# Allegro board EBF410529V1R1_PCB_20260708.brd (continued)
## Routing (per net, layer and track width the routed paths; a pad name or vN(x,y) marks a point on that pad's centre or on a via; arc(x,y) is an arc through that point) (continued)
HDMI_TX_D3P_PORT: length 18.5
  BOTTOM w0.107: C222.2 105.76,63.27 arc(105.56,63.57) 105.49,63.92 105.49,64.5 arc(105.56,64.85) 105.76,65.15 R228.1 105.9,65.58 arc(105.8,65.73) 105.77,65.9 D51.2 105.57,66.5 arc(105.51,66.58) 105.49,66.69 105.49,69.63 arc(105.43,69.9) 105.28,70.13 104.68,70.73 102.92,72.49 102.52,72.9 arc(102.42,73.04) 102.38,73.22 102.38,74.83 arc(102.31,75.21) 102.09,75.53 101.96,75.67 arc(101.77,75.79) 101.55,75.84 99.05,75.84 arc(98.78,75.89) 98.54,76.05 J33.10
HDMI_TX_EARC+: length 14.4
  BOTTOM w0.107: J33.14 98.51,73.77 arc(98.82,73.3) 98.93,72.74 98.93,71.56 arc(98.92,71.41) 98.87,71.27 arc(98.81,71.16) 98.73,71.07 arc(98.5,70.73) 98.42,70.34 98.42,69.31 arc(98.6,68.89) 99.03,68.71 101.05,68.71 arc(101.17,68.74) 101.28,68.81 101.3,68.83 arc(101.37,68.94) 101.4,69.06 arc(101.53,69.39) 101.86,69.52 102.24,69.52 arc(102.74,69.32) 102.95,68.82 102.95,66.68 arc(102.97,66.58) 103.02,66.5 D44.2 103.12,66.18 arc(103.07,66.1) 103.05,66.01 103.05,65.99 arc(103.07,65.9) 103.12,65.83 C224.2
HDMI_TX_EARC-: length 16.6
  BOTTOM w0.107: R149.2 101.6,63.49 101.6,64.9 102.11,65.41 C225.2 102.62,65.44 arc(102.72,65.48) 102.76,65.58 102.76,65.76 arc(102.73,65.9) 102.65,66.03 D31.2 102.55,66.46 arc(102.63,66.59) 102.66,66.74 102.66,66.81 arc(102.63,66.89) 102.55,66.92 arc(102.47,66.95) 102.44,67.03 102.44,67.24 arc(102.47,67.32) 102.55,67.35 arc(102.63,67.38) 102.66,67.46 102.66,67.73 arc(102.63,67.81) 102.55,67.84 arc(102.47,67.88) 102.44,67.96 102.44,68.16 arc(102.47,68.24) 102.55,68.27 arc(102.63,68.3) 102.66,68.38 102.66,68.82 arc(102.54,69.12) 102.24,69.24 101.86,69.24 arc(101.73,69.19) 101.68,69.06 arc(101.63,68.83) 101.5,68.63 101.48,68.61 arc(101.28,68.47) 101.05,68.43 100.81,68.43 arc(100.74,68.4) 100.71,68.33 arc(100.68,68.25) 100.61,68.22 100.28,68.22 arc(100.21,68.25) 100.18,68.33 arc(100.15,68.4) 100.08,68.43 99.03,68.43 arc(98.4,68.69) 98.14,69.31 98.14,69.77 arc(98.1,69.87) 98,69.91 arc(97.91,69.95) 97.87,70.04 97.87,70.19 arc(97.91,70.29) 98,70.33 arc(98.1,70.37) 98.14,70.47 98.14,70.65 arc(98.09,70.92) 97.93,71.16 97.82,71.27 arc(97.67,71.33) 97.52,71.27 J33.19
HDMI_TX_HPDIN_M0: length 182.3
  TOP w0.107: v1(44.5,59.05) 45.44,58.1 J3.125 ; Q8.3 v1(109.02,53.84) R141.2
  ART03 w0.107: v1(108.91,8.13) 108.91,8.49 108.05,9.35 108.05,21.36 106.83,22.58 106.83,35.64 110.24,39.04 110.87,39.04 113.16,41.33 113.16,46.82 v1(112.5,47.48)
  BOTTOM w0.107: v1(109.02,53.84) 109.93,52.93 109.93,49.63 112.08,47.48 v1(112.5,47.48) ; v1(108.91,8.13) 108.5,8.54 104.73,8.54 103.4,7.21 66.98,7.21 64.31,4.55 47.9,4.55 46.86,5.59 46.86,6.99 42.65,11.2 42.65,22.02 40.92,23.74 40.92,27.79 42.21,29.08 42.21,48.54 40.85,49.91 40.85,55.4 v1(44.5,59.05)
HDMI_TX_ON_H: length 171.1
  TOP w0.107: v1(43.7,59.05) 44.94,57.8 J3.123 ; R164.1 v1(100.01,52.84)
  ART03 w0.107: v1(104.41,7.13) 104.14,7.4 104.14,12.32 103.89,12.57 103.89,20.6 103.07,21.41 103.07,49.99 102.79,50.27 102.79,51.92 102.34,52.37 100.47,52.37 v1(100.01,52.84)
  BOTTOM w0.107: v1(43.7,59.05) 43.7,58.76 40.59,55.65 40.59,49.71 41.88,48.41 41.88,29.24 40.67,28.02 40.67,23.42 42.3,21.78 42.3,10.96 46.53,6.73 46.53,5.36 47.73,4.17 64.35,4.17 67.04,6.85 104.14,6.85 v1(104.41,7.13)
HDMI_TX_SBDN: length 52.7
  TOP w0.107: v1(80.8,61.44) 80.69,61.44 arc(80.59,61.48) 80.55,61.58 80.55,62.42 arc(80.57,62.51) 80.61,62.58 80.63,62.59 arc(80.67,62.66) 80.69,62.75 J3.258
  BOTTOM w0.107: v1(80.8,61.44) 80.8,61.33 81.04,61.09 arc(81.18,60.88) 81.23,60.64 81.23,60.56 arc(81.19,60.37) 81.08,60.2 80.94,60.06 arc(80.8,59.97) 80.64,59.94 78.87,59.94 arc(78.62,59.99) 78.4,60.14 78.38,60.15 arc(78.23,60.37) 78.18,60.63 78.18,61.8 arc(78.16,61.92) 78.09,62.02 77.64,62.46 arc(77.47,62.58) 77.26,62.62 76.29,62.62 arc(76.15,62.59) 76.03,62.51 75.18,61.67 arc(75.06,61.49) 75.02,61.28 75.02,60.29 arc(75.15,59.65) 75.51,59.11 76.2,58.42 arc(76.8,58.02) 77.51,57.88 103.03,57.88 arc(103.1,57.9) 103.12,57.97 arc(103.17,58.07) 103.27,58.12 103.41,58.12 arc(103.51,58.07) 103.55,57.97 arc(103.58,57.9) 103.64,57.88 103.88,57.88 arc(104.06,57.95) 104.13,58.13 104.13,58.86 arc(104.1,58.95) 104.01,58.99 arc(103.92,59.02) 103.89,59.11 103.89,59.29 arc(103.92,59.38) 104.01,59.41 arc(104.1,59.45) 104.13,59.54 104.13,59.72 arc(104.1,59.8) 104.01,59.84 arc(103.92,59.88) 103.89,59.96 103.89,60.14 arc(103.92,60.23) 104.01,60.27 arc(104.1,60.3) 104.13,60.39 104.13,60.48 arc(104.1,60.65) 104,60.8 103.91,60.89 arc(103.82,60.92) 103.73,60.89 arc(103.64,60.85) 103.55,60.89 103.43,61.01 arc(103.39,61.1) 103.43,61.19 arc(103.47,61.28) 103.43,61.37 103.09,61.71 arc(102.77,62.18) 102.66,62.74 102.66,64.17 arc(102.58,64.36) 102.4,64.44 C225.1
HDMI_TX_SBDP: length 52.1
  TOP w0.107: v1(80.8,60.63) 80.69,60.74 80.69,60.81 80.47,61.03 arc(80.32,61.26) 80.26,61.53 80.26,62.48 80.19,62.56 J3.256
  BOTTOM w0.107: C224.1 103.16,64.09 arc(103,63.86) 102.95,63.58 102.95,62.74 arc(103.04,62.29) 103.29,61.91 104.21,61 arc(104.36,60.76) 104.42,60.48 104.42,58.13 arc(104.26,57.75) 103.88,57.59 77.51,57.59 arc(76.69,57.75) 76,58.22 75.31,58.91 arc(74.89,59.54) 74.74,60.29 74.74,61.28 arc(74.8,61.6) 74.98,61.87 75.83,62.72 arc(76.04,62.86) 76.29,62.91 77.26,62.91 arc(77.58,62.84) 77.84,62.66 78.29,62.22 arc(78.42,62.03) 78.46,61.8 78.46,60.63 arc(78.49,60.48) 78.58,60.36 78.6,60.34 arc(78.72,60.25) 78.87,60.22 80.64,60.22 arc(80.69,60.23) 80.74,60.26 80.88,60.4 arc(80.91,60.48) 80.88,60.55 v1(80.8,60.63)
HDMI_TX_SCL: length 99.3
  TOP w0.107: v1(41.62,59.25) 41.82,59.05 43.05,59.05 44.44,57.67 J3.121
  ART03 w0.107: v1(41.62,59.25) 41.81,59.44 46.46,59.44 47.17,58.72 54.84,58.72 55.64,59.53 55.64,62.91 56.79,64.06 71.91,64.06 75.79,60.17 75.79,50.1 v1(77.89,48.01)
  BOTTOM w0.107: v1(77.89,48.01) 77.57,48.01 74.73,50.85 74.73,54.56 71.99,57.3 71.99,62.59 76.4,67.01 78.37,67.01 78.89,66.49 78.89,64.29 80.04,63.14 88.19,63.14 Q6.2 89.79,63.94 R139.2
HDMI_TX_SCL_PORT: length 19.4
  TOP w0.107: v1(87.36,70.17) 87.36,69.85 87.58,69.64 D45.2 87.96,70.33 88.21,70.59 91.19,70.59 93.98,73.38 J33.15
  BOTTOM w0.107: R140.2 86.02,64.9 Q6.3 86.96,67.35 87.36,67.75 v1(87.36,70.17)
HDMI_TX_SDA: length 108.4
  TOP w0.107: J3.119 43.94,57.66 42.93,58.67 41.2,58.67 v1(40.62,59.25)
  ART03 w0.107: v1(78.89,48.01) 78.4,47.52 77.75,47.52 75.53,49.74 75.53,59.87 71.68,63.73 57,63.73 56.03,62.76 56.03,59.33 54.53,57.84 52.91,57.84 52.5,58.24 47.22,58.24 46.79,58.67 41.2,58.67 v1(40.62,59.25)
  BOTTOM w0.107: R146.2 95.39,63.94 Q7.2 91.91,63.94 90.83,62.87 79.93,62.87 78.61,64.19 78.61,66.37 78.28,66.7 76.46,66.7 72.26,62.5 72.26,57.53 75.13,54.66 75.13,51 77.67,48.46 78.43,48.46 v1(78.89,48.01)
HDMI_TX_SDA_PORT: length 20.9
  TOP w0.107: J33.16 93.91,72.8 91.36,70.26 89.76,70.26 89.51,70 D46.2 89.08,69.64 88.89,69.82 88.89,70.14 v1(88.86,70.17)
  BOTTOM w0.107: v1(88.86,70.17) 89.36,69.67 89.36,67.89 89.69,67.56 91.62,67.56 92.65,66.54 Q7.3 91.84,64.9 R147.2
HP_BUTTON_DET: length 54.1
  TOP w0.107: v1(42.78,81.95) 40.43,79.6 38.94,79.6 38.53,79.2 38.53,78.67 38.86,78.33 39.98,78.33 42.55,75.77 53.31,75.77 54.38,74.7 54.38,72.24 54.94,71.68 54.94,68.35 52.83,66.24 41.43,66.24 40.69,65.51 J3.106
  TOP w0.203: R83.2 C77.1 45.03,83.68 45.03,82.53 R86.1 v1(45.11,81.95)
  BOTTOM w0.107: v1(45.11,81.95) 44.94,81.79 42.94,81.79 v1(42.78,81.95)
HP_PLUG_IN_DET: length 48.9
  TOP w0.107: J3.131 v1(46.94,54.54) ; v1(48.87,74.63) 48.08,75.41 42.32,75.41 39.78,77.95 38.73,77.95 38.18,78.51 38.18,79.38 38.73,79.93 40.18,79.93 41.86,81.61 41.86,83.16 42.18,83.48 v1(42.18,83.55)
  BOTTOM w0.107: v1(46.94,54.54) 46.94,54.74 47.52,55.32 50.19,55.32 51.92,57.05 51.92,58.95 51.66,59.2 51.66,59.56 51.18,60.05 51.18,60.66 50.98,60.86 50.98,62.8 51.89,63.71 51.89,65.3 47.57,69.62 47.57,72.65 48.87,73.94 v1(48.87,74.63) ; R88.2 v1(42.18,83.55)
I2C2_SCL_M0: length 200.2
  TOP w0.107: v1(55.9,67.73) 55.51,67.73 53.37,65.58 48.23,65.58 47.69,65.04 J3.134 47.69,62.44 v1(47.69,62.44) ; J13.9 141.34,16.55 140.26,15.47 140.26,13.97 138.63,12.34 138.63,11.21 v1(139.28,10.57)
  ART03 w0.107: v1(49.09,8.34) 49.96,9.22 49.96,15.21 51.08,16.33 58.27,16.33 59.44,15.16 59.44,12.62 60.5,11.56 67.01,11.56 72.52,6.05 115.68,6.05 117.06,7.42 131.62,7.42 134.32,10.11 138.82,10.11 v1(139.28,10.57)
  BOTTOM w0.107: v1(49.09,8.34) 47.7,9.73 47.7,21.13 46.63,22.2 44.07,22.2 41.88,24.38 41.88,27.33 43.21,28.65 43.21,49.05 42.29,49.97 42.29,53.85 41.94,54.2 41.94,55.15 45.43,58.64 45.43,59.9 46.2,60.68 47.09,60.68 47.69,61.28 v1(47.69,62.44) 47.69,62.67 47.12,63.25 46.49,63.25 R239.2 ; v1(55.9,67.73) 55.48,67.31 51.54,67.31 49.69,69.15 49.69,70.14 49.84,70.29 U11.6
I2C2_SDA_M0: length 198.6
  TOP w0.107: J13.10 141.23,17.05 139.8,15.62 139.8,14.02 138.28,12.5 v1(138.28,10.57) ; v1(48.19,61.44) J3.136 48.19,64.94 48.53,65.28 53.54,65.28 55.59,67.32 56.49,67.32 v1(56.9,67.73)
  ART03 w0.107: v1(138.28,10.57) 134.16,10.57 131.39,7.8 116.87,7.8 115.49,6.43 72.62,6.43 67.18,11.86 60.81,11.86 59.79,12.88 59.79,15.29 58.44,16.64 50.83,16.64 49.55,15.36 49.55,10.81 v1(49.09,10.34)
  BOTTOM w0.107: v1(49.09,10.34) 48.27,10.34 48.06,10.55 48.06,21.31 46.79,22.58 44.12,22.58 42.77,23.93 42.77,27.61 43.51,28.35 43.51,49.25 42.65,50.11 42.65,53.87 42.21,54.31 42.21,55.06 45.74,58.58 45.74,59.81 46.28,60.35 47.32,60.35 48.19,61.22 v1(48.19,61.44) 48.19,62.88 47.83,63.25 47.51,63.25 R240.2 ; U11.7 49.34,68.97 51.31,67.01 56.17,67.01 v1(56.9,67.73)
I2C3_SCL_M0: length 124.1
  TOP w0.107: v1(2.04,42.05) 2.44,41.65 2.44,40.64 1.57,39.77 1.57,15.55 2.27,14.85 J14.6 ; v1(29.35,62.14) 29.69,62.48 J3.62 29.69,65.08 29.21,65.56 27.1,65.56 v1(26.69,65.15)
  ART03 w0.107: v1(29.35,62.14) 29.35,61.46 28.74,60.85 26.5,60.85 25.98,60.33 23.06,60.33 22.43,60.96 16.71,60.96 16.28,61.39 13.08,61.39 11,59.31 11,56.46 9.23,54.69 9.23,52.22 5.59,48.59 4.55,48.59 3.45,47.5 3.45,44.78 2.49,43.81 2.49,43.32 2.7,43.1 3.1,43.1 3.45,42.75 3.45,42.29 3.21,42.05 v1(2.04,42.05)
  BOTTOM w0.107: U5.6 5.54,52.14 5.44,52.25 3.89,52.25 2.9,53.24 1.83,53.24 1.57,52.98 1.57,44.35 2.44,43.48 2.44,42.45 v1(2.04,42.05) ; v1(26.69,65.15) 26.69,65.05 R162.2 25.14,64.52 24.21,64.52 22.81,63.12 21.21,63.12 20.38,62.29 20.38,55.63 21.23,54.78 26.33,54.78 27.66,56.11 27.66,56.53 U9.28
I2C3_SDA_M0: length 119.9
  TOP w0.107: J3.64 30.19,65.11 29.44,65.86 25.16,65.86 v1(24.45,65.15) ; v1(2.02,43.05) 1.6,42.63 1.6,41.81 2.08,41.33 2.08,40.85 1.17,39.93 1.17,15.24 2.06,14.35 J14.5
  ART03 w0.107: v1(24.45,65.15) 22.95,63.65 12.27,63.65 10.02,61.4 10.02,55.99 8.89,54.86 8.89,52.34 5.52,48.97 4.29,48.97 3.12,47.8 3.12,45.11 2.02,44.01 v1(2.02,43.05)
  BOTTOM w0.107: v1(2.02,43.05) 2.02,43.42 1.23,44.21 1.23,53.13 1.69,53.58 3.04,53.58 4.06,52.55 5.46,52.55 5.7,52.79 U5.5 ; v1(24.45,65.15) 24.21,65.15 23.77,64.72 23.44,64.72 R160.2 22.22,63.5 21.11,63.5 20.12,62.51 20.12,55.52 21.12,54.52 26.56,54.52 27.99,55.96 27.99,56.84 U9.27
I2C4_SCL_M2: length 83.6
  TOP w0.107: J15.6 5.43,34.05 4.88,33.5 4.01,33.5 v1(3.55,33.05) ; v1(50.19,61.44) 51.19,62.44 J3.148
  ART03 w0.107: v1(50.19,61.44) 49.66,61.97 49.66,62.84 48.65,63.85 35.35,63.85 34.67,63.18 34.67,59.26 30.84,55.43 15,55.43 13.48,53.91 13.48,50.94 12.98,50.44 12.98,43.24 11.79,42.04 7.52,42.04 4.32,38.84 2.95,38.84 1.96,37.85 1.96,33.76 2.66,33.05 v1(3.55,33.05)
  BOTTOM w0.107: v1(50.19,61.44) 50.6,61.85 50.6,63.31 R188.2
I2C4_SDA_M2: length 82.4
  TOP w0.107: v1(50.19,62.24) 50.69,62.74 J3.146 ; J15.5 5.43,33.55 4.93,33.05 v1(4.55,33.05)
  ART03 w0.107: v1(4.55,33.05) 4.09,32.59 2.57,32.59 1.65,33.5 1.65,38.02 2.79,39.17 4.24,39.17 7.4,42.33 11.71,42.33 12.73,43.34 12.73,50.54 13.23,51.05 13.23,54.08 14.91,55.76 30.64,55.76 34.26,59.39 34.26,63.29 35.21,64.24 48.82,64.24 50.19,62.86 v1(50.19,62.24)
  BOTTOM w0.107: v1(50.19,62.24) 50.19,63.61 R163.2
I2C5_SCL_M3: length 114.8
  TOP w0.107: v1(46.69,62.44) 46.69,62.44 J3.130
  ART03 w0.107: v1(44.09,10.81) v1(36.8,10.81)
  BOTTOM w0.107: R190.2 44.81,62.89 45.82,62.89 46.05,62.66 46.47,62.66 v1(46.69,62.44) 46.46,62.2 46.05,62.2 45.64,61.8 45.64,61.11 44.91,60.38 44.91,58.85 41.11,55.05 41.11,50.18 42.55,48.74 42.55,28.93 41.18,27.56 41.18,24.05 43.01,22.23 43.01,15.87 43.64,15.24 43.64,11.27 v1(44.09,10.81) ; v1(36.8,10.81) 35.48,10.81 34.46,9.8 6.89,9.8 6.3,10.39 6.3,11.52 3.35,14.46 3.35,20.93 3.77,21.35 J16.6
I2C5_SDA_M3: length 123.1
  TOP w0.107: J3.132 v1(47.19,61.44)
  ART03 w0.107: v1(47.24,10.31) v1(35.8,10.31)
  BOTTOM w0.107: v1(35.8,10.31) 35.61,10.31 34.72,9.42 6.76,9.42 5.84,10.34 5.84,11.38 2.97,14.25 2.97,21.11 3.71,21.85 J16.5 ; v1(47.24,10.31) 47.28,10.36 47.28,20.98 46.42,21.84 43.92,21.84 41.53,24.23 41.53,27.43 42.88,28.78 42.88,48.86 41.96,49.78 41.96,53.8 41.63,54.13 41.63,55.21 45.17,58.75 45.17,60.1 46.08,61.01 46.76,61.01 v1(47.19,61.44) 47.19,62.71 46.94,62.97 46.23,62.97 45.95,63.25 45.47,63.25 R189.2
I2C7_SCL_M1: length 265.5
  TOP w0.107: J3.66 v1(30.69,65.15) ; v1(3.02,43.55) 2.7,43.55 1.91,44.35 1.91,51.17 3.41,52.68 5.38,52.68 5.57,52.87 J18.6
  ART03 w0.107: v1(30.69,65.15) 30.69,62.14 28.47,59.92 16.94,59.92 16.23,59.21 14.25,59.21 9.48,54.44 9.48,52.05 5.61,48.18 4.7,48.18 3.8,47.29 3.8,44.39 3.02,43.61 v1(3.02,43.55) ; v1(101.93,31.14) 101.93,26.01 92.13,16.21 88.84,16.21 88.82,16.21 76.12,16.21 75.59,16.74 60.21,16.74 59.55,17.4 44.2,17.4 42.8,16 36.32,16 34.42,17.91 20.85,17.91 v1(20.48,17.54)
  BOTTOM w0.107: J32.5 145.82,58.14 147.85,58.14 148.29,57.71 148.29,43.37 147.71,42.8 144.34,42.8 142.48,44.65 132.17,44.65 130.82,43.31 120.81,43.31 116.75,39.24 112.19,39.24 111.61,38.66 111.61,35.99 108.61,32.99 108.03,32.99 106.17,31.14 v1(101.93,31.14) ; v1(20.48,17.54) 20.02,18 20.02,18.67 19.61,19.08 19.61,40.79 16.05,44.35 13.18,44.35 12.62,44.91 6.17,44.91 4.81,43.55 v1(3.02,43.55) ; R236.2 29.96,65.15 v1(30.69,65.15)
I2C7_SDA_M1: length 275.9
  TOP w0.107: J3.68 31.19,65.25 30.79,65.65 30.26,65.65 29.76,66.15 24.45,66.15 v1(23.45,65.15) ; v1(3.02,42.55) 4.68,42.55 5.71,43.59 5.71,49.39 4.5,50.61 4.5,51.92 4.95,52.37 J18.5
  ART03 w0.107: v1(19.48,18.54) 19.99,19.05 21.82,19.05 22.2,18.67 35.31,18.67 36.32,17.65 43.08,17.65 43.84,18.41 51.69,18.41 51.94,18.67 59.44,18.67 60.53,17.58 76.15,17.58 76.43,17.3 91.95,17.3 101.12,26.46 101.12,30.95 v1(100.93,31.14) ; v1(3.02,42.55) 1.87,42.55 1.6,42.82 1.6,44.04 2.79,45.24 2.79,48.01 4.14,49.35 5.42,49.35 8.59,52.52 8.59,55.04 9.09,55.55 9.09,61.77 11.81,64.49 18.67,64.49 19.08,64.08 22.38,64.08 v1(23.45,65.15)
  BOTTOM w0.107: v1(19.48,18.54) 19.23,18.79 19.23,40.49 15.77,43.94 12.83,43.94 12.27,44.5 6.35,44.5 4.4,42.55 v1(3.02,42.55) ; v1(23.45,65.15) 23.32,65.02 R235.2 ; J32.3 146.05,60.45 148.48,60.45 148.69,60.24 148.69,43.21 147.88,42.39 144.17,42.39 142.32,44.25 132.33,44.25 130.99,42.9 120.98,42.9 116.9,38.82 112.4,38.82 112.04,38.47 112.04,35.86 108.58,32.41 108.08,32.41 106.32,30.66 101.41,30.66 v1(100.93,31.14)
I2C8_SCL_M2: length 145.8
  TOP w0.107: v1(49.19,61.44) 49.61,61.85 49.61,62.26 50.19,62.84 J3.144
  ART03 w0.107: v1(49.09,11.34) 47.56,9.81 v1(36.8,9.81)
  BOTTOM w0.107: R238.2 49.63,63.15 49.63,61.88 v1(49.19,61.44) 49.19,61.13 47.73,59.66 46.47,59.66 46.25,59.45 46.25,58.37 43.36,55.47 43.36,50.32 44.7,48.97 44.7,27.71 44.25,27.25 44.25,23.8 44.7,23.34 47.17,23.34 48.64,21.87 48.64,11.79 v1(49.09,11.34) ; J17.6 4.84,40.55 4.57,40.28 2.82,40.28 2.18,39.65 2.18,9.8 2.95,9.04 34.95,9.04 35.74,9.83 36.79,9.83 v1(36.8,9.81)
I2C8_SDA_M2: length 149.3
  TOP w0.107: v1(49.19,62.24) 49.19,62.25 49.69,62.75 J3.142
  ART03 w0.107: v1(35.8,9.31) 49.06,9.31 v1(49.09,9.34)
  BOTTOM w0.107: J17.5 4.83,41.05 4.39,40.61 2.69,40.61 1.85,39.78 1.85,9.6 2.77,8.69 35.18,8.69 v1(35.8,9.31) ; v1(49.09,9.34) 49.5,9.76 49.5,10.69 49.33,10.87 48.55,10.87 48.34,11.08 48.34,21.59 47.02,22.91 44.32,22.91 43.13,24.1 43.13,25.35 43.84,26.06 43.84,49.41 43,50.24 43,53.9 42.52,54.38 42.52,55 45.99,58.48 45.99,59.61 46.38,59.99 47.47,59.99 48.67,61.19 48.67,61.71 v1(49.19,62.24) 49.19,63.06 49,63.26 48.51,63.26 R237.2
LCD_BL_PWM: length 136.3
  TOP w0.107: v1(138.67,26.51) 139.3,25.87 139.3,19.93 140.69,18.55 J13.13 ; J3.169 57.94,20.34 v1(58.93,19.35)
  ART03 w0.107: v1(100.65,26.66) 92.27,18.28 76.27,18.28 75.95,17.96 60.85,17.96 59.74,19.08 59.21,19.08 v1(58.93,19.35)
  BOTTOM w0.107: v1(138.67,26.51) 138.39,26.51 137.77,27.13 137.77,28.4 137.26,28.91 128.12,28.91 125.15,25.93 123.05,25.93 122.43,25.31 110.2,25.31 108.85,26.66 v1(100.65,26.66)
LCD_PWR_EN: length 197.5
  TOP w0.107: v1(73.52,71.74) 73.52,69.43 75.13,67.82 80.42,67.82 81.14,67.09 81.14,65.83 81.86,65.11 91.37,65.11 92.54,66.28 95.02,66.28 96.23,67.49 103.61,67.49 105.97,69.85 105.97,70.89 v1(107.04,71.96) ; J3.228 73.19,66.43 71.99,67.63 v1(71.99,71.74) ; v1(129.27,57.11) 128.81,56.65 128.81,51.3 137.06,43.05 137.06,38.91 136.37,38.23 136.37,26.75 v1(136.88,26.24)
  BOTTOM w0.107: v1(136.88,26.24) 138.1,25.02 139.27,25.02 140.84,23.44 146.05,23.44 147.24,22.26 147.24,9.32 146.65,8.74 138.91,8.74 138.38,9.27 137.77,9.27 137.22,8.72 112.87,8.72 112.24,9.35 112.24,19.81 113.03,20.6 116.93,20.6 R153.1 ; v1(107.04,71.96) 110.11,68.88 110.11,60.3 113.3,57.11 v1(129.27,57.11) ; v1(71.99,71.74) v1(73.52,71.74)
LCD_RST: length 135.7
  TOP w0.107: v1(139.67,26.51) 139.69,26.49 139.69,20.13 140.27,19.55 J13.15 ; v1(61.21,18.85) 60.99,19.08 59.82,19.08 58.44,20.45 J3.171
  ART03 w0.107: v1(61.21,18.85) 61.71,18.35 75.74,18.35 76.06,18.67 91.65,18.67 v1(99.65,26.66)
  BOTTOM w0.107: v1(99.65,26.66) 100.16,27.18 108.88,27.18 110.36,25.7 122.27,25.7 122.91,26.34 124.97,26.34 127.94,29.31 137.52,29.31 138.25,28.57 138.25,27.2 138.51,26.95 139.23,26.95 v1(139.67,26.51)
LOUT1: length 35.6
  TOP w0.203: v1(46.63,67.26) 47.11,67.74 52.58,67.74 53.03,68.19 C81.2
  ART03 w0.203: v1(46.63,67.26) 45.56,66.19 37.08,66.19 35.89,67.39 32.21,67.39 31.67,67.92 28.07,67.92 25.65,65.51 25.65,64.62 25.2,64.16 v1(25.2,61.93)
  BOTTOM w0.107: v1(25.2,61.93) 25.2,61.54 U9.12
LOUT2: length 15.1
  TOP w0.254: C86.1 v1(17.92,67.04)
  BOTTOM w0.254: U9.15 26.87,62.06 26.87,64.04 27.59,64.76 27.59,65.6 27.36,65.84 27,66.19 20.14,66.19 19.3,67.04 v1(17.92,67.04)
MASKROM: length 13.5
  BOTTOM w0.107: SW1.2 142.78,70.61 D11.2 137.82,65.65 C25.1 R27.1
MIC1N: length 29.9
  TOP w0.203: R85.2 v1(43.43,77.25)
  BOTTOM w0.203: v1(43.43,77.25) 43.74,76.95 43.74,76.06 44.27,75.52 44.27,67.18 41.73,64.64 36.12,64.64 34.09,62.61 34.09,60.48 32.56,58.95 32.56,57.93 32.23,57.6 31.71,57.6 C74.2
MIC1P: length 30.6
  TOP w0.203: R81.2 v1(44.45,77.25)
  BOTTOM w0.203: v1(44.45,77.25) 44.15,76.95 44.15,76.23 44.68,75.69 44.68,67.01 41.9,64.24 36.29,64.24 34.49,62.44 34.49,60.31 32.97,58.79 32.97,57.77 32.4,57.2 31.71,57.2 C71.2
MIC2N: length 40.3
  BOTTOM w0.203: C76.2 31.85,59.94 32.92,61.01 32.92,63.12 35.92,66.12 41.4,66.12 42.88,67.59 42.88,75.08 41.2,76.76 41.2,81.21 40.79,81.62 40.79,83.21 40.39,83.62 38.64,83.62 38.07,84.19 38.07,84.89 R101.1 C89.2 38.05,86.52 38.05,88.05 P1.2
MIC2P: length 41.2
  BOTTOM w0.203: C75.2 33.32,60.85 33.32,62.95 36.08,65.71 41.57,65.71 43.28,67.42 43.28,75.25 41.61,76.93 41.61,81.38 41.2,81.79 41.2,83.38 40.55,84.02 38.81,84.02 38.48,84.35 38.48,84.93 R99.2 C89.1 38.46,86.52 38.46,88.05 P1.1
MINIPCIE_3V3: length 51.8
  TOP w0.381: J20.2 114.82,17.57 114.38,17.12 111.33,17.12 109.64,18.8 C172.1 R179.1 108.75,16.76 v1(108.89,16.89) ; J20.24 126.82,19.97 127.13,20.27 C173.1 127.63,22.11 v1(127.91,21.82)
  TOP w0.508: J20.39 132.82,12.05 133.22,12.45 ; 133.22,12.45 133.22,14.88 133.99,15.65 137.26,15.65 138.02,16.41 J20.52 138.02,20.22 136.65,21.59 C174.1 C175.1 134.29,22.11 v1(133.3,21.12) v1(133.3,20.32) ; 133.22,12.45 133.62,12.04 J20.41
  BOTTOM w0.254: R172.2 C164.2 113.52,30.38 113.52,32.47 115.3,34.25 v1(121.65,34.25)
  vias: v1(121.65,33.25) v1(121.65,32.25) v1(122.65,34.25) v1(122.65,33.25) v1(122.65,32.25)
MINIPCIE_NWDISABLE: length 183.5
  TOP w0.107: R182.2 125.59,23.61 v1(125.59,24.61) ; v1(47.94,53.54) 47.44,54.04 J3.133
  BOTTOM w0.107: v1(47.94,53.54) 49.43,52.05 49.43,33.15 48.5,32.22 48.5,29.27 52.07,25.7 52.07,23.39 59.87,15.6 59.87,15.11 61.65,13.34 64.21,13.34 64.82,12.73 68.61,12.73 69.09,12.24 73.18,12.24 75.39,14.45 86.33,14.45 87.1,13.69 87.1,13.34 87.66,12.78 87.66,11.18 90.6,8.23 103.15,8.23 104.19,9.27 111.07,9.27 112.42,7.92 134.03,7.92 134.82,7.14 137.29,7.14 138.05,7.9 146.99,7.9 148.06,8.97 148.06,22.58 146.4,24.24 141.85,24.24 140.12,25.97 138.37,25.97 137.26,27.08 128.42,27.08 125.96,24.61 v1(125.59,24.61)
MINIPCIE_PWR_EN: length 200.1
  TOP w0.107: J3.135 v1(47.94,54.54)
  BOTTOM w0.107: v1(47.94,54.54) 47.94,54.14 47.5,53.7 47.5,53.11 49.02,51.59 49.02,33.3 48.09,32.37 48.09,29.12 51.66,25.55 51.66,23.27 59.44,15.49 59.44,15.04 62.18,12.29 68.17,12.29 68.73,11.73 73.38,11.73 75.77,14.12 86.11,14.12 86.66,13.56 86.66,13.2 87.22,12.64 87.22,11.05 90.45,7.82 103.38,7.82 104.47,8.92 110.82,8.92 112.22,7.52 133.83,7.52 134.65,6.71 137.52,6.71 138.34,7.53 147.25,7.53 148.46,8.74 148.46,24.61 145.85,27.23 141.55,27.23 138.25,30.53 129.31,30.53 128.73,31.11 126.67,31.11 125.76,32.03 124.92,32.03 124.13,32.82 118.67,32.82 117.98,32.13 115.47,32.13 115.05,31.72 R177.1
MIPI_DPHY_CSI0_RX_CLKN: length 105.7
  TOP w0.107: v1(11.69,19.14) 11.61,19.07 arc(11.54,19.02) 11.46,19 11.34,19 arc(11.16,18.97) 11.01,18.87 10.1,17.96 arc(9.97,17.76) 9.91,17.52 arc(9.87,17.43) 9.81,17.35 9.33,16.87 arc(9.19,16.78) 9.02,16.74 7.53,16.74 arc(7.47,16.75) 7.42,16.79 7.4,16.8 arc(7.35,16.84) 7.29,16.85 J14.10 ; v1(72.41,44.47) 72.62,44.26 arc(72.84,44.11) 73.1,44.06 77.38,44.06 arc(79.57,44.5) 81.42,45.74 arc(82.47,47.3) 82.83,49.15 82.83,54.57 arc(82.85,54.63) 82.88,54.68 82.89,54.7 arc(82.93,54.75) 82.94,54.81 J3.269
  ART03 w0.102: v1(11.69,19.14) 11.77,19.06 arc(11.84,19.02) 11.93,19 arc(11.93,19) 11.93,19 12.64,19 arc(13.2,18.77) 13.43,18.2 13.43,18.03 arc(13.69,17.78) 13.94,18.03 13.94,18.34 arc(14.1,18.72) 14.47,18.87 14.55,18.87 arc(14.89,18.94) 15.19,19.14 19.4,23.35 arc(19.78,23.92) 19.91,24.59 19.91,27.87 arc(20.07,28.24) 20.45,28.4 20.6,28.4 arc(20.78,28.47) 20.85,28.65 20.85,28.72 arc(20.8,28.85) 20.66,28.91 20.45,28.91 arc(19.91,29.44) 20.45,29.97 20.6,29.97 arc(20.78,30.05) 20.85,30.23 20.85,30.24 arc(20.78,30.41) 20.61,30.48 20.45,30.48 arc(20.07,30.64) 19.91,31.02 19.91,31.02 arc(19.99,31.42) 20.21,31.75 28.21,39.74 arc(28.86,40.18) 29.64,40.34 56.73,40.34 arc(57.64,40.52) 58.41,41.03 60.88,43.5 arc(61.79,44.11) 62.86,44.32 72.17,44.32 arc(72.25,44.34) 72.33,44.39 v1(72.41,44.47)
MIPI_DPHY_CSI0_RX_CLKP: length 105.8
  TOP w0.107: v1(73.22,44.47) 73.29,44.4 arc(73.35,44.36) 73.42,44.35 77.38,44.35 arc(79.46,44.76) 81.22,45.94 arc(82.2,47.41) 82.55,49.15 82.55,54.57 arc(82.54,54.63) 82.5,54.68 82.49,54.7 arc(82.45,54.75) 82.44,54.81 J3.267 ; J14.9 7.29,16.35 arc(7.35,16.36) 7.4,16.4 7.42,16.41 arc(7.47,16.45) 7.53,16.46 9.02,16.46 arc(9.3,16.51) 9.53,16.67 10.01,17.15 arc(10.13,17.3) 10.19,17.49 arc(10.22,17.63) 10.3,17.76 11.21,18.67 arc(11.27,18.71) 11.34,18.72 11.56,18.72 arc(11.65,18.68) 11.69,18.58 v1(11.69,18.34)
  ART03 w0.102: v1(11.69,18.34) 11.69,18.52 arc(11.75,18.66) 11.9,18.72 12.64,18.72 arc(13,18.57) 13.15,18.2 13.15,18.03 arc(13.69,17.5) 14.22,18.03 14.22,18.34 arc(14.3,18.52) 14.47,18.59 14.55,18.59 arc(15,18.68) 15.38,18.94 19.6,23.15 arc(20.04,23.81) 20.19,24.59 20.19,27.87 arc(20.27,28.05) 20.45,28.12 20.6,28.12 arc(20.98,28.28) 21.13,28.65 21.13,28.72 arc(21,29.05) 20.66,29.19 20.45,29.19 arc(20.19,29.44) 20.45,29.7 20.6,29.7 arc(20.98,29.85) 21.13,30.23 21.13,30.24 arc(20.98,30.61) 20.61,30.76 20.45,30.76 arc(20.27,30.84) 20.19,31.02 20.19,31.02 arc(20.25,31.31) 20.41,31.55 28.4,39.54 arc(28.97,39.92) 29.64,40.06 56.73,40.06 arc(57.75,40.26) 58.61,40.83 60.83,43.05 61.08,43.3 arc(61.9,43.85) 62.87,44.04 72.37,44.04 arc(72.55,44.08) 72.71,44.19 72.92,44.4 arc(73,44.45) 73.1,44.47 v1(73.22,44.47)
MIPI_DPHY_CSI0_RX_D0N: length 105.9
  TOP w0.107: v1(9.02,18) 8.88,17.87 arc(8.75,17.77) 8.59,17.74 7.53,17.74 arc(7.47,17.75) 7.42,17.79 7.4,17.8 arc(7.35,17.84) 7.29,17.85 J14.12 ; v1(73.22,41.97) 73.33,42.09 arc(73.44,42.16) 73.57,42.18 79.66,42.18 arc(81.25,42.5) 82.59,43.4 83.85,44.66 arc(84.58,45.75) 84.83,47.03 84.83,54.57 arc(84.85,54.63) 84.88,54.68 84.89,54.7 arc(84.93,54.75) 84.94,54.81 J3.277
  ART03 w0.102: v1(9.02,18) 9.1,17.92 arc(9.18,17.87) 9.26,17.86 9.5,17.86 11.57,15.78 arc(11.64,15.74) 11.72,15.72 13.19,15.72 arc(14.24,15.93) 15.13,16.52 21.98,23.38 arc(22.36,23.95) 22.5,24.62 22.5,30.84 arc(22.64,31.59) 23.07,32.23 29.04,38.2 arc(29.66,38.61) 30.4,38.76 57.2,38.76 arc(58.3,38.98) 59.24,39.6 60.87,41.24 arc(61.7,41.79) 62.68,41.99 71.78,41.99 arc(71.84,42) 71.9,42.04 72.15,42.28 arc(72.25,42.35) 72.37,42.38 72.42,42.38 arc(72.57,42.35) 72.69,42.27 72.91,42.05 arc(72.99,41.99) 73.09,41.97 v1(73.22,41.97)
MIPI_DPHY_CSI0_RX_D0P: length 105.9
  TOP w0.107: J14.11 7.29,17.35 arc(7.35,17.36) 7.4,17.4 7.42,17.41 arc(7.47,17.45) 7.53,17.46 8.58,17.46 arc(8.75,17.43) 8.88,17.33 v1(9.02,17.2) ; J3.275 84.44,54.81 arc(84.45,54.75) 84.49,54.7 84.5,54.68 arc(84.54,54.63) 84.55,54.57 84.55,47.03 arc(84.32,45.86) 83.65,44.86 82.39,43.6 arc(81.14,42.76) 79.66,42.47 73.25,42.47 arc(72.93,42.41) 72.67,42.23 v1(72.41,41.97)
  ART03 w0.102: v1(9.02,17.2) 9.02,17.37 arc(9.08,17.52) 9.23,17.58 9.38,17.58 11.38,15.58 arc(11.53,15.48) 11.72,15.44 13.19,15.44 arc(14.35,15.67) 15.33,16.33 22.18,23.18 arc(22.62,23.84) 22.77,24.62 22.77,30.84 arc(22.9,31.48) 23.26,32.03 29.24,38 arc(29.77,38.36) 30.4,38.48 57.2,38.48 arc(58.41,38.72) 59.43,39.4 61.07,41.04 arc(61.81,41.53) 62.68,41.71 70.78,41.71 arc(70.86,41.67) 70.9,41.59 arc(70.93,41.51) 71.01,41.48 71.29,41.48 arc(71.37,41.51) 71.4,41.59 arc(71.44,41.67) 71.52,41.71 71.78,41.71 arc(71.95,41.74) 72.1,41.84 72.24,41.98 arc(72.32,42.01) 72.4,41.98 v1(72.41,41.97)
MIPI_DPHY_CSI0_RX_D1N: length 105.8
  TOP w0.107: v1(72.41,43.47) 72.62,43.26 arc(72.84,43.11) 73.1,43.06 78.66,43.06 arc(80.45,43.42) 81.97,44.43 82.9,45.36 arc(83.59,46.4) 83.83,47.62 83.83,54.57 arc(83.85,54.63) 83.88,54.68 83.89,54.7 arc(83.93,54.75) 83.94,54.81 J3.273 ; J14.8 7.29,15.85 arc(7.35,15.84) 7.4,15.8 7.42,15.79 arc(7.47,15.75) 7.53,15.74 9.23,15.74 arc(9.8,15.86) 10.28,16.18 10.77,16.66 arc(10.91,16.76) 11.08,16.79 11.2,16.79 arc(11.38,16.83) 11.54,16.93 v1(11.69,17.08)
  ART03 w0.102: v1(11.69,17.08) 11.75,17.02 arc(11.81,16.98) 11.88,16.97 13.69,16.97 arc(14.36,17.1) 14.93,17.48 21.48,24.04 arc(21.6,24.21) 21.64,24.42 21.64,24.42 arc(21.57,24.6) 21.39,24.68 21.29,24.68 arc(20.75,25.21) 21.29,25.74 21.39,25.74 arc(21.57,25.82) 21.64,26 21.64,26.05 arc(21.56,26.25) 21.36,26.33 21.29,26.33 arc(20.75,26.86) 21.29,27.4 21.41,27.4 arc(21.57,27.46) 21.64,27.62 21.64,31.22 arc(21.8,31.99) 22.24,32.65 28.54,38.95 arc(29.2,39.39) 29.97,39.55 56.94,39.55 arc(58,39.76) 58.9,40.36 61.07,42.53 arc(61.9,43.09) 62.89,43.28 72.09,43.28 arc(72.21,43.3) 72.31,43.37 v1(72.41,43.47)
MIPI_DPHY_CSI0_RX_D1P: length 105.9
  TOP w0.107: v1(11.69,16.27) 11.57,16.4 arc(11.45,16.48) 11.31,16.5 11.08,16.5 arc(11.02,16.49) 10.97,16.46 10.49,15.98 arc(9.91,15.59) 9.23,15.46 7.53,15.46 arc(7.47,15.45) 7.42,15.41 7.4,15.4 arc(7.35,15.36) 7.29,15.35 J14.7 ; v1(73.22,43.47) 73.29,43.4 arc(73.35,43.36) 73.42,43.35 78.66,43.35 arc(80.34,43.68) 81.77,44.63 82.69,45.56 arc(83.33,46.51) 83.55,47.62 83.55,54.57 arc(83.54,54.63) 83.5,54.68 83.49,54.7 arc(83.45,54.75) 83.44,54.81 J3.271
  ART03 w0.102: v1(73.22,43.47) 73.09,43.47 arc(72.99,43.45) 72.91,43.4 72.72,43.2 arc(72.5,43.05) 72.24,43 72,43 arc(71.93,42.97) 71.9,42.9 arc(71.87,42.83) 71.8,42.8 71.5,42.8 arc(71.42,42.83) 71.4,42.9 arc(71.37,42.97) 71.29,43 62.89,43 arc(62.01,42.83) 61.27,42.33 59.1,40.16 arc(58.11,39.5) 56.94,39.27 29.97,39.27 arc(29.3,39.13) 28.73,38.76 22.43,32.45 arc(22.05,31.89) 21.92,31.22 21.92,27.62 arc(21.77,27.26) 21.41,27.12 21.29,27.12 arc(21.03,26.86) 21.29,26.61 21.36,26.61 arc(21.76,26.44) 21.92,26.05 21.92,26 arc(21.76,25.62) 21.39,25.46 21.29,25.46 arc(21.03,25.21) 21.29,24.96 21.39,24.96 arc(21.76,24.8) 21.92,24.42 21.92,24.42 arc(21.86,24.1) 21.68,23.84 15.12,17.28 arc(14.46,16.84) 13.69,16.69 11.86,16.69 arc(11.74,16.64) 11.69,16.52 v1(11.69,16.27)
MIPI_DPHY_CSI0_RX_D2N: length 105.8
  TOP w0.107: J14.17 7.29,20.35 arc(7.35,20.34) 7.4,20.3 7.42,20.29 arc(7.47,20.25) 7.53,20.24 9.97,20.24 arc(10.19,20.29) 10.39,20.42 10.47,20.5 arc(10.55,20.62) 10.58,20.76 10.58,20.78 arc(10.55,20.92) 10.47,21.04 v1(10.32,21.19) ; v1(73.22,45.47) 73.3,45.55 arc(73.37,45.6) 73.45,45.61 77.97,45.61 arc(79.12,45.84) 80.1,46.5 80.48,46.87 arc(81.11,47.82) 81.33,48.94 81.33,54.57 arc(81.35,54.63) 81.38,54.68 81.39,54.7 arc(81.43,54.75) 81.44,54.81 J3.263
  ART03 w0.102: v1(73.22,45.47) 73.1,45.47 arc(73.01,45.45) 72.94,45.4 72.74,45.2 arc(72.58,45.1) 72.39,45.06 62.83,45.06 arc(61.84,44.86) 61,44.3 58.36,41.66 arc(57.54,41.11) 56.57,40.92 29.15,40.92 arc(28.74,40.84) 28.38,40.6 19.51,31.72 arc(19.34,31.47) 19.28,31.17 19.28,30.8 arc(19.08,30.32) 18.59,30.11 18.07,30.11 arc(17.9,30.04) 17.83,29.87 17.83,29.86 arc(17.91,29.68) 18.08,29.61 18.55,29.61 arc(19.07,29.39) 19.28,28.88 19.28,25.92 arc(19.03,25.32) 18.43,25.07 17.7,25.07 arc(17.5,24.99) 17.42,24.8 arc(17.44,24.7) 17.5,24.61 17.54,24.57 arc(17.61,24.53) 17.69,24.51 18.27,24.51 arc(18.63,24.37) 18.77,24.02 18.77,23.87 arc(18.62,23.51) 18.25,23.35 17.96,23.35 arc(17.78,23.28) 17.7,23.1 17.7,23.09 arc(17.62,22.69) 17.4,22.35 16,20.95 arc(15.44,20.58) 14.78,20.45 14.49,20.45 arc(14.31,20.37) 14.24,20.19 14.24,20.16 arc(13.7,19.63) 13.17,20.16 13.17,20.21 arc(13.1,20.38) 12.93,20.45 12.92,20.45 arc(12.74,20.37) 12.66,20.19 12.66,20.16 arc(12.13,19.63) 11.59,20.16 11.59,20.22 arc(11.53,20.38) 11.37,20.45 10.95,20.45 arc(10.76,20.48) 10.6,20.59 10.58,20.61 arc(10.48,20.77) 10.44,20.95 10.44,20.99 arc(10.43,21.06) 10.39,21.12 v1(10.32,21.19)
MIPI_DPHY_CSI0_RX_D2P: length 105.9
  TOP w0.107: J3.261 80.94,54.81 arc(80.95,54.75) 80.99,54.7 81,54.68 arc(81.04,54.63) 81.05,54.57 81.05,48.94 arc(80.85,47.93) 80.28,47.08 79.9,46.7 arc(79.01,46.11) 77.97,45.9 73.13,45.9 arc(72.86,45.84) 72.63,45.69 v1(72.41,45.47) ; v1(11.13,21.19) 10.98,21.05 arc(10.89,20.92) 10.86,20.77 10.86,20.76 arc(10.81,20.51) 10.68,20.3 10.59,20.21 arc(10.3,20.02) 9.97,19.96 7.53,19.96 arc(7.47,19.95) 7.42,19.91 7.4,19.9 arc(7.35,19.86) 7.29,19.85 J14.16
  ART03 w0.102: v1(72.41,45.47) 72.34,45.4 arc(72.27,45.35) 72.19,45.34 71.06,45.34 arc(71,45.37) 70.97,45.43 arc(70.94,45.49) 70.88,45.52 70.55,45.52 arc(70.49,45.49) 70.46,45.43 arc(70.44,45.37) 70.37,45.34 62.83,45.34 arc(61.73,45.12) 60.81,44.5 58.16,41.86 arc(57.43,41.37) 56.57,41.2 29.15,41.2 arc(28.63,41.09) 28.18,40.8 19.31,31.92 arc(19.08,31.58) 19,31.17 19,30.8 arc(18.88,30.51) 18.59,30.39 18.07,30.39 arc(17.7,30.24) 17.55,29.87 17.55,29.86 arc(17.71,29.48) 18.08,29.33 18.55,29.33 arc(18.87,29.2) 19,28.88 19,25.92 arc(18.83,25.52) 18.43,25.35 17.7,25.35 arc(17.31,25.19) 17.14,24.8 arc(17.19,24.59) 17.3,24.42 17.34,24.37 arc(17.5,24.27) 17.69,24.23 18.27,24.23 arc(18.43,24.17) 18.49,24.02 18.49,23.87 arc(18.42,23.7) 18.25,23.63 17.96,23.63 arc(17.58,23.48) 17.42,23.1 17.42,23.09 arc(17.37,22.8) 17.2,22.55 15.8,21.15 arc(15.33,20.84) 14.78,20.73 14.49,20.73 arc(14.11,20.57) 13.96,20.19 13.96,20.16 arc(13.7,19.91) 13.45,20.16 13.45,20.21 arc(13.3,20.57) 12.93,20.73 12.92,20.73 arc(12.54,20.57) 12.38,20.19 12.38,20.16 arc(12.13,19.91) 11.87,20.16 11.87,20.22 arc(11.73,20.58) 11.37,20.73 10.95,20.73 arc(10.87,20.74) 10.8,20.79 10.78,20.81 arc(10.73,20.87) 10.72,20.95 10.72,21.04 arc(10.76,21.15) 10.87,21.19 v1(11.13,21.19)
MIPI_DPHY_CSI0_RX_D3N: length 105.7
  TOP w0.107: v1(9.02,22) 8.88,21.87 arc(8.75,21.77) 8.59,21.74 7.53,21.74 arc(7.47,21.75) 7.42,21.79 7.4,21.8 arc(7.35,21.84) 7.29,21.85 J14.20 ; J3.259 80.44,54.81 arc(80.43,54.75) 80.39,54.7 80.38,54.68 arc(80.35,54.63) 80.33,54.57 80.33,49.55 arc(79.47,47.46) 77.38,46.6 73.42,46.6 arc(73.35,46.58) 73.29,46.54 v1(73.22,46.47)
  ART03 w0.102: v1(9.02,22) 9.16,21.86 arc(9.3,21.77) 9.46,21.74 9.67,21.74 arc(9.72,21.75) 9.77,21.78 9.86,21.87 arc(10,21.96) 10.16,22 11.92,22 arc(12.1,22.07) 12.18,22.25 12.18,22.76 arc(12.71,23.29) 13.24,22.76 13.24,22.25 arc(13.5,22) 13.75,22.25 13.75,22.71 arc(14.29,23.24) 14.82,22.71 14.82,22.25 arc(14.89,22.07) 15.07,22 15.08,22 arc(15.29,22.04) 15.46,22.15 15.99,22.68 arc(16.09,22.84) 16.13,23.02 16.13,24.61 arc(16.6,25.75) 17.75,26.23 17.91,26.23 arc(18.16,26.48) 17.91,26.73 16.81,26.73 arc(16.28,27.27) 16.81,27.8 17.91,27.8 arc(18.16,28.06) 17.91,28.31 16.89,28.31 arc(16.51,28.47) 16.36,28.84 16.36,29.27 arc(16.5,29.99) 16.91,30.6 27.78,41.47 arc(28.44,41.91) 29.21,42.06 56.68,42.06 arc(57.24,42.17) 57.72,42.49 60.86,45.63 arc(61.74,46.22) 62.78,46.43 70.74,46.43 arc(70.93,46.47) 71.08,46.57 71.18,46.66 arc(71.42,46.83) 71.72,46.89 72.39,46.89 arc(72.58,46.85) 72.74,46.75 72.94,46.54 arc(73.02,46.49) 73.1,46.47 v1(73.22,46.47)
MIPI_DPHY_CSI0_RX_D3P: length 105.7
  TOP w0.107: v1(9.02,21.2) 8.88,21.33 arc(8.75,21.43) 8.58,21.46 7.53,21.46 arc(7.47,21.45) 7.42,21.41 7.4,21.4 arc(7.35,21.36) 7.29,21.35 J14.19 ; J3.257 79.94,54.81 arc(79.95,54.75) 79.99,54.7 80,54.68 arc(80.04,54.63) 80.05,54.57 80.05,49.55 arc(79.27,47.66) 77.38,46.88 73.17,46.88 arc(73.05,46.86) 72.95,46.79 72.71,46.54 arc(72.63,46.49) 72.53,46.47 v1(72.41,46.47)
  ART03 w0.102: v1(72.41,46.47) 72.33,46.55 arc(72.27,46.59) 72.19,46.61 71.72,46.61 arc(71.53,46.57) 71.37,46.47 71.28,46.38 arc(71.03,46.21) 70.74,46.15 70.32,46.15 arc(70.24,46.12) 70.21,46.05 arc(70.18,45.98) 70.11,45.95 69.81,45.95 arc(69.74,45.98) 69.71,46.05 arc(69.68,46.12) 69.6,46.15 69.3,46.15 arc(69.23,46.12) 69.2,46.05 arc(69.17,45.98) 69.1,45.95 68.79,45.95 arc(68.72,45.98) 68.69,46.05 arc(68.66,46.12) 68.59,46.15 62.78,46.15 arc(61.85,45.97) 61.06,45.44 57.92,42.3 arc(57.35,41.92) 56.68,41.78 29.21,41.78 arc(28.54,41.65) 27.97,41.27 17.1,30.4 arc(16.76,29.88) 16.64,29.27 16.64,28.84 arc(16.71,28.66) 16.89,28.59 17.91,28.59 arc(18.44,28.06) 17.91,27.52 16.81,27.52 arc(16.56,27.27) 16.81,27.01 17.91,27.01 arc(18.44,26.48) 17.91,25.95 17.75,25.95 arc(16.8,25.55) 16.41,24.61 16.41,23.02 arc(16.35,22.73) 16.18,22.48 15.66,21.96 arc(15.39,21.78) 15.08,21.72 15.07,21.72 arc(14.7,21.87) 14.54,22.25 14.54,22.71 arc(14.29,22.96) 14.03,22.71 14.03,22.25 arc(13.5,21.72) 12.97,22.25 12.97,22.76 arc(12.71,23.01) 12.46,22.76 12.46,22.25 arc(12.3,21.87) 11.92,21.72 10.16,21.72 arc(10.1,21.71) 10.06,21.67 9.97,21.58 arc(9.83,21.49) 9.67,21.46 9.46,21.46 arc(9.3,21.43) 9.16,21.33 v1(9.02,21.2)
MIPI_DPHY_CSI1_RX_CLKN: length 78
  TOP w0.107: J15.10 7.29,36.05 arc(7.35,36.04) 7.4,36 7.42,35.99 arc(7.47,35.95) 7.53,35.94 8.8,35.94 arc(8.95,35.97) 9.08,36.06 v1(9.22,36.2) ; v1(70.96,53.94) 70.94,53.94 arc(70.86,53.97) 70.83,54.04 70.83,54.57 arc(70.85,54.63) 70.88,54.68 70.89,54.7 arc(70.93,54.75) 70.94,54.81 J3.221
  ART03 w0.102: v1(9.22,36.2) 9.22,36.06 arc(9.24,35.95) 9.3,35.86 9.32,35.85 arc(9.41,35.78) 9.52,35.76 11.68,35.76 arc(11.86,35.8) 12.01,35.9 12.5,36.39 arc(12.85,36.62) 13.25,36.7 13.49,36.7 arc(13.69,36.74) 13.85,36.85 14.41,37.41 arc(15.03,37.83) 15.77,37.97 16.4,37.97 arc(16.56,38) 16.69,38.09 18.62,40.02 arc(18.68,40.17) 18.62,40.31 18.5,40.43 arc(18.5,41.19) 19.26,41.19 19.35,41.09 arc(19.52,41.02) 19.69,41.09 19.7,41.1 arc(19.78,41.28) 19.7,41.46 19.57,41.6 arc(19.57,42.35) 20.32,42.35 20.46,42.21 arc(20.63,42.14) 20.81,42.21 20.81,42.22 arc(20.89,42.4) 20.81,42.57 20.64,42.75 arc(20.64,43.5) 21.4,43.5 21.58,43.32 arc(21.75,43.25) 21.92,43.32 24.48,45.88 arc(25.99,46.89) 27.77,47.24 54.57,47.24 arc(55.35,47.4) 56.02,47.84 60.32,52.15 arc(61.35,52.84) 62.56,53.08 67.86,53.08 arc(67.93,53.11) 67.97,53.18 arc(68,53.26) 68.07,53.29 68.37,53.29 arc(68.44,53.26) 68.47,53.18 arc(68.5,53.11) 68.58,53.08 68.91,53.08 arc(69.12,53.12) 69.3,53.24 69.39,53.33 arc(69.66,53.51) 69.98,53.57 70.86,53.57 arc(70.93,53.6) 70.96,53.67 v1(70.96,53.94)
MIPI_DPHY_CSI1_RX_CLKP: length 78.1
  TOP w0.107: v1(70.96,53.13) 70.96,53.25 arc(70.94,53.34) 70.89,53.42 70.64,53.67 arc(70.57,53.77) 70.55,53.89 70.55,54.57 arc(70.54,54.63) 70.5,54.68 70.49,54.7 arc(70.45,54.75) 70.44,54.81 J3.219 ; v1(9.22,35.39) 9.07,35.53 arc(8.93,35.62) 8.77,35.66 7.53,35.66 arc(7.47,35.65) 7.42,35.61 7.4,35.6 arc(7.35,35.56) 7.29,35.55 J15.9
  ART03 w0.102: v1(70.96,53.13) 70.87,53.22 arc(70.79,53.27) 70.69,53.29 69.98,53.29 arc(69.77,53.25) 69.59,53.13 69.5,53.04 arc(69.23,52.86) 68.91,52.8 62.56,52.8 arc(61.46,52.58) 60.52,51.95 56.21,47.65 arc(55.46,47.14) 54.57,46.96 27.77,46.96 arc(26.1,46.63) 24.68,45.69 22.11,43.12 arc(21.75,42.97) 21.38,43.12 21.2,43.3 arc(20.84,43.3) 20.84,42.95 21.01,42.77 arc(21.17,42.4) 21.01,42.02 21,42.01 arc(20.63,41.86) 20.27,42.01 20.12,42.15 arc(19.76,42.15) 19.76,41.79 19.9,41.66 arc(20.05,41.28) 19.9,40.9 19.89,40.9 arc(19.52,40.74) 19.15,40.9 19.06,40.99 arc(18.7,40.99) 18.7,40.63 18.82,40.51 arc(18.96,40.17) 18.82,39.83 16.89,37.9 arc(16.67,37.75) 16.4,37.69 15.77,37.69 arc(15.14,37.57) 14.61,37.21 14.05,36.66 arc(13.79,36.48) 13.49,36.42 13.25,36.42 arc(12.95,36.36) 12.7,36.2 12.21,35.7 arc(11.97,35.54) 11.68,35.48 9.37,35.48 arc(9.32,35.47) 9.27,35.44 v1(9.22,35.39)
MIPI_DPHY_CSI1_RX_D0N: length 78
  TOP w0.107: v1(13.15,35.85) 13.02,35.71 arc(12.88,35.62) 12.72,35.59 12.34,35.59 arc(11.94,35.67) 11.59,35.9 10.84,36.65 arc(10.52,36.87) 10.14,36.94 7.53,36.94 arc(7.47,36.95) 7.42,36.99 7.4,37 arc(7.35,37.04) 7.29,37.05 J15.12 ; v1(71.96,52.94) 71.88,53.02 arc(71.83,53.09) 71.81,53.18 71.81,54.53 arc(71.83,54.61) 71.87,54.67 71.88,54.69 arc(71.93,54.75) 71.94,54.83 J3.225
  ART03 w0.102: v1(13.15,35.85) 13.15,35.65 arc(13.21,35.51) 13.34,35.46 15.08,35.46 arc(15.26,35.49) 15.41,35.59 arc(15.49,35.77) 15.41,35.95 15.29,36.08 arc(15.13,36.46) 15.29,36.83 arc(15.67,37) 16.06,36.84 16.17,36.74 arc(16.35,36.66) 16.53,36.73 25.15,45.36 arc(26.4,46.19) 27.86,46.48 54.95,46.48 arc(55.67,46.63) 56.29,47.04 60.42,51.17 arc(61.42,51.83) 62.59,52.07 67.65,52.07 arc(67.72,52.09) 67.74,52.16 arc(67.77,52.22) 67.83,52.25 68.16,52.25 arc(68.23,52.22) 68.25,52.16 arc(68.28,52.09) 68.34,52.07 68.67,52.07 arc(68.73,52.09) 68.76,52.16 arc(68.79,52.22) 68.85,52.25 69.18,52.25 arc(69.24,52.22) 69.27,52.16 arc(69.29,52.09) 69.36,52.07 69.59,52.07 arc(69.79,52.11) 69.96,52.22 70.05,52.31 arc(70.32,52.49) 70.63,52.55 71.86,52.55 arc(71.93,52.58) 71.96,52.65 v1(71.96,52.94)
MIPI_DPHY_CSI1_RX_D0P: length 77.9
  TOP w0.107: v1(13.15,35.04) 13.02,35.18 arc(12.88,35.27) 12.72,35.31 12.34,35.31 arc(11.83,35.41) 11.39,35.7 10.64,36.45 arc(10.41,36.6) 10.14,36.66 7.47,36.66 7.4,36.6 arc(7.35,36.56) 7.29,36.55 J15.11 ; v1(71.96,52.13) 71.96,52.25 arc(71.94,52.34) 71.89,52.42 71.68,52.63 arc(71.57,52.8) 71.53,52.99 71.53,54.61 arc(71.52,54.66) 71.49,54.7 71.48,54.71 arc(71.45,54.75) 71.44,54.8 J3.223
  ART03 w0.102: v1(71.96,52.13) 71.88,52.21 arc(71.81,52.26) 71.72,52.27 70.63,52.27 arc(70.43,52.23) 70.25,52.12 70.16,52.03 arc(69.9,51.85) 69.59,51.79 62.59,51.79 arc(61.52,51.57) 60.61,50.97 56.49,46.84 arc(55.78,46.37) 54.95,46.2 27.86,46.2 arc(26.5,45.93) 25.35,45.16 16.72,36.54 arc(16.35,36.38) 15.97,36.54 15.87,36.64 arc(15.67,36.72) 15.48,36.64 arc(15.41,36.46) 15.48,36.28 15.61,36.15 arc(15.77,35.77) 15.61,35.4 arc(15.37,35.24) 15.08,35.18 13.37,35.18 arc(13.3,35.16) 13.23,35.12 v1(13.15,35.04)
MIPI_DPHY_CSI1_RX_D1N: length 77.9
  TOP w0.107: J15.8 7.29,35.05 arc(7.35,35.04) 7.4,35 7.42,34.99 arc(7.47,34.95) 7.53,34.94 10.45,34.94 arc(10.87,34.86) 11.23,34.62 11.31,34.53 arc(11.58,34.35) 11.9,34.29 14.02,34.29 arc(14.16,34.35) 14.22,34.49 v1(14.22,34.55) ; J3.229 72.94,54.82 arc(72.93,54.75) 72.89,54.7 72.88,54.68 arc(72.84,54.63) 72.83,54.56 72.83,53.16 arc(72.84,53.08) 72.89,53.01 v1(72.96,52.94)
  ART03 w0.102: v1(72.96,52.94) 72.96,52.83 arc(72.95,52.75) 72.9,52.68 72.65,52.44 arc(72.57,52.31) 72.54,52.17 72.54,51.86 72.4,51.71 arc(72.26,51.62) 72.1,51.59 71.23,51.59 arc(70.89,51.52) 70.61,51.33 70.52,51.24 arc(70.32,51.11) 70.09,51.06 62.16,51.06 arc(61.45,50.92) 60.84,50.51 56.55,46.22 arc(55.99,45.85) 55.34,45.72 28.15,45.72 arc(26.76,45.44) 25.58,44.65 15.4,34.48 arc(15.03,34.23) 14.58,34.14 14.35,34.14 arc(14.26,34.17) 14.22,34.26 v1(14.22,34.55)
MIPI_DPHY_CSI1_RX_D1P: length 77.9
  TOP w0.107: v1(14.22,33.74) 14.09,33.88 arc(13.95,33.97) 13.79,34.01 11.9,34.01 arc(11.47,34.09) 11.11,34.33 11.03,34.42 arc(10.76,34.6) 10.45,34.66 7.53,34.66 arc(7.47,34.65) 7.42,34.61 7.4,34.6 arc(7.35,34.56) 7.29,34.55 J15.7 ; J3.227 72.44,54.81 arc(72.45,54.75) 72.48,54.7 72.5,54.69 arc(72.53,54.64) 72.54,54.58 72.54,52.97 arc(72.58,52.77) 72.69,52.61 72.9,52.4 arc(72.94,52.33) 72.96,52.24 v1(72.96,52.13)
  ART03 w0.102: v1(72.96,52.13) 72.88,52.05 arc(72.84,51.98) 72.82,51.9 72.82,51.74 72.6,51.51 arc(72.37,51.36) 72.1,51.31 71.23,51.31 arc(71,51.26) 70.8,51.13 70.71,51.04 arc(70.43,50.85) 70.09,50.78 62.16,50.78 arc(61.55,50.66) 61.04,50.31 56.75,46.02 arc(56.1,45.59) 55.34,45.44 28.15,45.44 arc(26.87,45.19) 25.78,44.46 15.6,34.28 arc(15.13,33.97) 14.58,33.86 14.41,33.86 arc(14.34,33.85) 14.29,33.81 v1(14.22,33.74)
MIPI_DPHY_CSI2_RX_CLKN: length 93.1
  TOP w0.107: J3.241 75.94,54.81 arc(75.95,54.75) 75.99,54.7 76,54.68 arc(76.04,54.63) 76.05,54.57 76.05,50.9 arc(75.91,50.2) 75.51,49.59 74.89,48.98 arc(74.38,48.64) 73.78,48.52 73.17,48.52 arc(73.1,48.53) 73.04,48.58 v1(72.96,48.65)
  ART03 w0.102: v1(15,24.88) 14.86,25.02 arc(14.77,25.16) 14.73,25.32 14.73,25.65 arc(14.81,26.01) 15.01,26.31 15.17,26.47 arc(15.48,26.94) 15.6,27.5 15.6,29.77 arc(15.73,30.44) 16.11,31.01 27.17,42.06 arc(28.04,42.65) 29.06,42.85 56.19,42.85 arc(56.98,43.01) 57.65,43.45 61.23,47.04 arc(61.8,47.42) 62.47,47.55 68.79,47.55 arc(68.86,47.52) 68.89,47.45 arc(68.92,47.38) 68.99,47.35 69.3,47.35 arc(69.37,47.38) 69.4,47.45 arc(69.43,47.52) 69.5,47.55 69.8,47.55 arc(69.88,47.52) 69.91,47.45 arc(69.94,47.38) 70.01,47.35 70.31,47.35 arc(70.38,47.38) 70.41,47.45 arc(70.44,47.52) 70.52,47.55 71.05,47.55 arc(71.42,47.62) 71.74,47.83 72.06,48.15 arc(72.15,48.21) 72.25,48.23 72.27,48.23 arc(72.38,48.26) 72.47,48.32 72.75,48.6 arc(72.81,48.63) 72.87,48.65 v1(72.96,48.65)
  BOTTOM w0.107: J16.10 7.29,19.35 arc(7.35,19.36) 7.4,19.4 7.42,19.41 arc(7.47,19.45) 7.53,19.46 8.15,19.46 8.33,19.63 12.87,19.63 arc(13.58,19.78) 14.18,20.18 14.24,20.24 arc(14.59,20.76) 14.71,21.37 14.71,24.4 arc(14.75,24.58) 14.85,24.73 v1(15,24.88)
MIPI_DPHY_CSI2_RX_CLKP: length 93.1
  TOP w0.107: v1(72.16,48.65) 72.28,48.65 arc(72.38,48.63) 72.46,48.57 72.71,48.33 arc(72.81,48.26) 72.92,48.23 73.78,48.23 arc(74.49,48.38) 75.1,48.78 75.71,49.39 arc(76.17,50.09) 76.33,50.9 76.33,54.57 arc(76.35,54.63) 76.38,54.68 76.39,54.7 arc(76.43,54.75) 76.44,54.81 J3.243
  ART03 w0.102: v1(72.16,48.65) 71.54,48.03 arc(71.31,47.88) 71.05,47.83 62.47,47.83 arc(61.7,47.67) 61.04,47.23 57.46,43.65 arc(56.88,43.26) 56.19,43.13 29.06,43.13 arc(27.93,42.9) 26.97,42.26 15.91,31.2 arc(15.47,30.55) 15.32,29.77 15.32,27.5 arc(15.23,27.05) 14.97,26.67 14.81,26.51 arc(14.55,26.12) 14.46,25.65 14.46,25.32 arc(14.42,25.16) 14.33,25.02 v1(14.19,24.88)
  BOTTOM w0.107: J16.9 7.29,19.85 arc(7.35,19.84) 7.4,19.8 7.42,19.79 arc(7.47,19.75) 7.53,19.74 8.04,19.74 8.21,19.92 12.87,19.92 arc(13.47,20.04) 13.98,20.38 14.04,20.44 arc(14.33,20.87) 14.43,21.37 14.43,24.48 arc(14.4,24.63) 14.32,24.75 v1(14.19,24.88)
MIPI_DPHY_CSI2_RX_D0N: length 93.1
  TOP w0.107: J3.233 73.94,54.81 arc(73.95,54.75) 73.99,54.7 74,54.68 arc(74.04,54.63) 74.05,54.57 74.05,53.84 arc(74.1,53.59) 74.24,53.37 74.34,53.28 arc(74.42,53.16) 74.45,53.01 74.45,51.67 arc(74.39,51.36) 74.21,51.1 73.7,50.59 arc(73.54,50.48) 73.35,50.44 73.28,50.44 arc(73.18,50.46) 73.09,50.52 v1(72.96,50.65)
  ART03 w0.102: v1(4.41,18.2) 4.41,18.43 arc(4.45,18.53) 4.55,18.57 4.74,18.57 arc(4.91,18.6) 5.06,18.7 5.08,18.72 arc(5.17,18.86) 5.21,19.03 5.21,19.48 arc(5.15,19.75) 5,19.99 4.9,20.08 arc(4.81,20.22) 4.78,20.39 4.78,21.67 arc(4.9,22.28) 5.24,22.79 5.41,22.96 arc(5.52,23.04) 5.66,23.06 5.69,23.06 arc(5.95,23.12) 6.17,23.26 26.27,43.37 arc(27.39,44.11) 28.7,44.37 55.38,44.37 arc(56.34,44.56) 57.15,45.11 61.03,48.98 arc(61.77,49.48) 62.66,49.66 70.65,49.66 arc(71.03,49.73) 71.35,49.94 71.55,50.15 arc(71.65,50.22) 71.77,50.24 72.19,50.24 arc(72.33,50.27) 72.44,50.34 72.68,50.58 arc(72.75,50.63) 72.84,50.65 v1(72.96,50.65)
  BOTTOM w0.107: v1(4.41,18.2) 4.41,18.33 4.54,18.46 5.65,18.46 5.76,18.35 J16.12
MIPI_DPHY_CSI2_RX_D0P: length 93.2
  TOP w0.107: v1(72.16,50.65) 72.27,50.65 arc(72.36,50.63) 72.43,50.58 72.62,50.39 arc(72.88,50.22) 73.18,50.16 73.35,50.16 arc(73.65,50.22) 73.91,50.39 74.41,50.9 arc(74.65,51.25) 74.73,51.67 74.73,53.01 arc(74.68,53.26) 74.54,53.48 74.44,53.57 arc(74.36,53.7) 74.33,53.84 74.33,54.57 arc(74.35,54.63) 74.38,54.68 74.39,54.7 arc(74.43,54.75) 74.44,54.81 J3.235
  ART03 w0.102: v1(4.41,19) 4.5,18.92 arc(4.58,18.87) 4.67,18.85 4.74,18.85 arc(4.81,18.86) 4.86,18.9 4.88,18.91 arc(4.91,18.97) 4.93,19.03 4.93,19.48 arc(4.89,19.65) 4.8,19.79 4.71,19.88 arc(4.55,20.11) 4.5,20.39 4.5,21.67 arc(4.64,22.38) 5.04,22.99 5.21,23.16 arc(5.42,23.29) 5.66,23.34 5.69,23.34 arc(5.84,23.37) 5.97,23.46 26.08,43.57 arc(27.28,44.37) 28.7,44.65 55.38,44.65 arc(56.23,44.82) 56.95,45.31 60.83,49.18 arc(61.67,49.74) 62.66,49.94 70.65,49.94 arc(70.92,49.99) 71.15,50.14 71.35,50.35 arc(71.55,50.48) 71.77,50.52 71.95,50.52 arc(72.02,50.54) 72.09,50.58 v1(72.16,50.65)
  BOTTOM w0.107: v1(4.41,19) 4.67,18.74 5.21,18.74 5.21,18.74 5.65,18.74 5.76,18.85 J16.11
MIPI_DPHY_CSI2_RX_D1N: length 93
  TOP w0.107: J3.237 74.94,54.81 arc(74.95,54.75) 74.99,54.7 75,54.68 arc(75.04,54.63) 75.05,54.57 75.05,53.86 75.26,53.65 75.26,51.59 arc(75.12,50.88) 74.72,50.28 74.13,49.69 arc(73.86,49.51) 73.54,49.45 73.3,49.45 arc(73.18,49.47) 73.07,49.54 v1(72.96,49.65)
  ART03 w0.102: v1(13.7,25.77) 13.56,25.77 arc(13.45,25.79) 13.36,25.85 13.34,25.87 arc(13.28,25.96) 13.26,26.07 13.26,27.16 arc(13.37,27.42) 13.63,27.53 14.18,27.53 arc(14.71,28.06) 14.18,28.6 14.02,28.6 arc(13.73,28.72) 13.61,29 13.61,29.03 arc(13.72,29.55) 14.01,29.99 26.65,42.63 arc(27.74,43.36) 29.03,43.61 55.77,43.61 arc(56.66,43.79) 57.41,44.29 61.15,48.02 arc(61.77,48.44) 62.51,48.59 70.75,48.59 arc(71.16,48.67) 71.5,48.9 71.77,49.17 arc(71.83,49.21) 71.91,49.23 72.17,49.23 arc(72.3,49.25) 72.41,49.32 72.66,49.57 arc(72.74,49.63) 72.84,49.65 v1(72.96,49.65)
  BOTTOM w0.107: J16.8 7.29,20.35 arc(7.35,20.36) 7.4,20.4 7.42,20.41 arc(7.47,20.45) 7.53,20.46 12.3,20.46 arc(13.07,20.78) 13.39,21.55 13.39,25.56 arc(13.45,25.71) 13.6,25.77 v1(13.7,25.77)
MIPI_DPHY_CSI2_RX_D1P: length 93
  TOP w0.107: v1(72.16,49.65) 72.28,49.65 arc(72.37,49.63) 72.44,49.58 72.62,49.4 arc(72.89,49.22) 73.19,49.16 73.54,49.16 arc(73.97,49.25) 74.33,49.49 74.92,50.08 arc(75.38,50.77) 75.54,51.59 75.54,53.77 75.33,53.98 75.33,54.57 arc(75.35,54.63) 75.38,54.68 75.39,54.7 arc(75.43,54.75) 75.44,54.81 J3.239
  ART03 w0.102: v1(12.9,25.77) 12.94,25.82 arc(12.97,25.85) 12.98,25.9 12.98,27.16 arc(13.17,27.62) 13.63,27.81 14.18,27.81 arc(14.43,28.06) 14.18,28.32 14.02,28.32 arc(13.53,28.52) 13.34,29 13.34,29.03 arc(13.46,29.65) 13.82,30.19 26.45,42.83 arc(27.63,43.61) 29.03,43.89 55.77,43.89 arc(56.55,44.05) 57.21,44.49 60.95,48.22 arc(61.67,48.7) 62.51,48.87 70.75,48.87 arc(71.05,48.93) 71.3,49.1 71.57,49.36 arc(71.72,49.47) 71.91,49.5 71.92,49.5 arc(72.01,49.52) 72.08,49.57 v1(72.16,49.65)
  BOTTOM w0.107: J16.7 7.29,20.85 arc(7.35,20.84) 7.4,20.8 7.42,20.79 arc(7.47,20.75) 7.53,20.74 12.3,20.74 arc(12.87,20.98) 13.11,21.55 13.11,25.42 arc(13.08,25.54) 13.01,25.65 v1(12.9,25.77)
MIPI_DPHY_CSI3_RX_CLKN: length 73.6
  TOP w0.107: v1(64.19,61.63) 64.69,62.13 J3.194 ; v1(22.06,46.26) 21.92,46.13 arc(21.78,46.03) 21.62,46 19.21,46 arc(18.7,46.1) 18.27,46.39 13.42,51.25 arc(13.06,51.79) 12.93,52.43 12.93,52.83 arc(12.78,53.56) 12.37,54.18 12.35,54.2 arc(11.73,54.62) 10.99,54.76 7.53,54.76 arc(7.47,54.77) 7.42,54.81 7.4,54.82 arc(7.35,54.86) 7.29,54.87 J18.10
  ART03 w0.102: v1(22.06,46.26) 22.2,46.12 arc(22.34,46.03) 22.5,46 22.81,46 arc(23.14,46.07) 23.42,46.25 24.88,47.72 arc(25.54,48.16) 26.32,48.31 54.32,48.31 arc(54.97,48.44) 55.53,48.81 63.67,56.95 arc(64.16,57.69) 64.34,58.57 64.34,59.42 arc(64.3,59.5) 64.22,59.53 arc(64.14,59.56) 64.11,59.65 64.11,59.82 arc(64.14,59.9) 64.22,59.94 arc(64.3,59.97) 64.34,60.05 64.34,61.39 arc(64.32,61.48) 64.27,61.55 v1(64.19,61.63)
MIPI_DPHY_CSI3_RX_CLKP: length 73.7
  TOP w0.107: v1(22.06,45.46) 21.92,45.59 arc(21.78,45.69) 21.62,45.72 19.21,45.72 arc(18.6,45.84) 18.07,46.19 13.22,51.04 arc(12.79,51.68) 12.64,52.43 12.64,52.83 arc(12.52,53.45) 12.17,53.98 12.15,54 arc(11.62,54.35) 10.99,54.48 7.53,54.48 arc(7.47,54.46) 7.42,54.43 7.4,54.42 arc(7.35,54.38) 7.29,54.37 6.56,54.37 J18.9 ; J3.192 v1(64.19,62.44)
  ART03 w0.102: v1(64.19,62.44) 64.19,62.32 arc(64.21,62.23) 64.26,62.16 64.47,61.94 arc(64.58,61.78) 64.62,61.6 64.62,58.57 arc(64.42,57.59) 63.87,56.75 55.72,48.61 arc(55.08,48.18) 54.32,48.03 26.32,48.03 arc(25.65,47.9) 25.08,47.52 23.61,46.05 arc(23.24,45.81) 22.81,45.72 22.5,45.72 arc(22.34,45.69) 22.2,45.59 v1(22.06,45.46)
MIPI_DPHY_CSI3_RX_D0N: length 78.6
  TOP w0.107: J18.12 7.29,55.87 arc(7.35,55.86) 7.4,55.82 7.42,55.81 arc(7.47,55.77) 7.53,55.76 11.25,55.76 arc(12.07,55.6) 12.76,55.14 13.1,54.8 arc(13.56,54.11) 13.72,53.29 13.72,52.3 arc(13.76,52.13) 13.85,51.98 15.92,49.91 arc(16.2,49.8) 16.47,49.91 16.81,50.25 arc(17.19,50.41) 17.57,50.25 arc(17.73,49.85) 17.57,49.45 17.24,49.12 arc(17.13,48.86) 17.24,48.59 17.26,48.57 arc(17.52,48.47) 17.78,48.57 19.24,50.03 arc(19.63,50.19) 20.02,50.03 arc(20.18,49.64) 20.02,49.25 18.49,47.72 arc(18.41,47.53) 18.49,47.34 18.49,47.34 arc(18.75,47.17) 19.06,47.1 19.62,47.1 arc(19.78,47.14) 19.92,47.23 v1(20.06,47.37) ; J3.186 62.69,62.13 v1(62.19,61.63)
  ART03 w0.102: v1(62.19,61.63) 62.27,61.55 arc(62.32,61.48) 62.33,61.4 62.33,60.96 arc(62.3,60.88) 62.23,60.85 arc(62.16,60.82) 62.13,60.75 62.13,60.55 arc(62.16,60.48) 62.23,60.45 arc(62.3,60.42) 62.33,60.35 62.33,60.14 arc(62.3,60.07) 62.23,60.04 arc(62.16,60.01) 62.13,59.94 62.13,59.74 arc(62.16,59.67) 62.23,59.64 arc(62.3,59.61) 62.33,59.53 62.33,58.51 arc(62.21,57.9) 61.87,57.39 54.67,50.19 arc(54.42,50.02) 54.12,49.96 25.3,49.96 arc(24.52,49.81) 23.87,49.37 22.7,48.2 arc(22.37,47.98) 21.98,47.9 21.85,47.9 arc(21.39,47.81) 21,47.55 20.65,47.2 arc(20.54,47.13) 20.41,47.1 arc(20.33,47.12) 20.26,47.16 v1(20.06,47.37)
